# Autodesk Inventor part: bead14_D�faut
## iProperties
Created: 2011-01
Part Number: bead14_D�faut
Document SubType Name: Modeling
Designer: eric
Density: 1 g/cm^3
Mass: 0.0245469 g
Surface Area: 1.38348 cm^2
Volume: 0.0245469 cm^3
Author: eric
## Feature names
1. Base1
